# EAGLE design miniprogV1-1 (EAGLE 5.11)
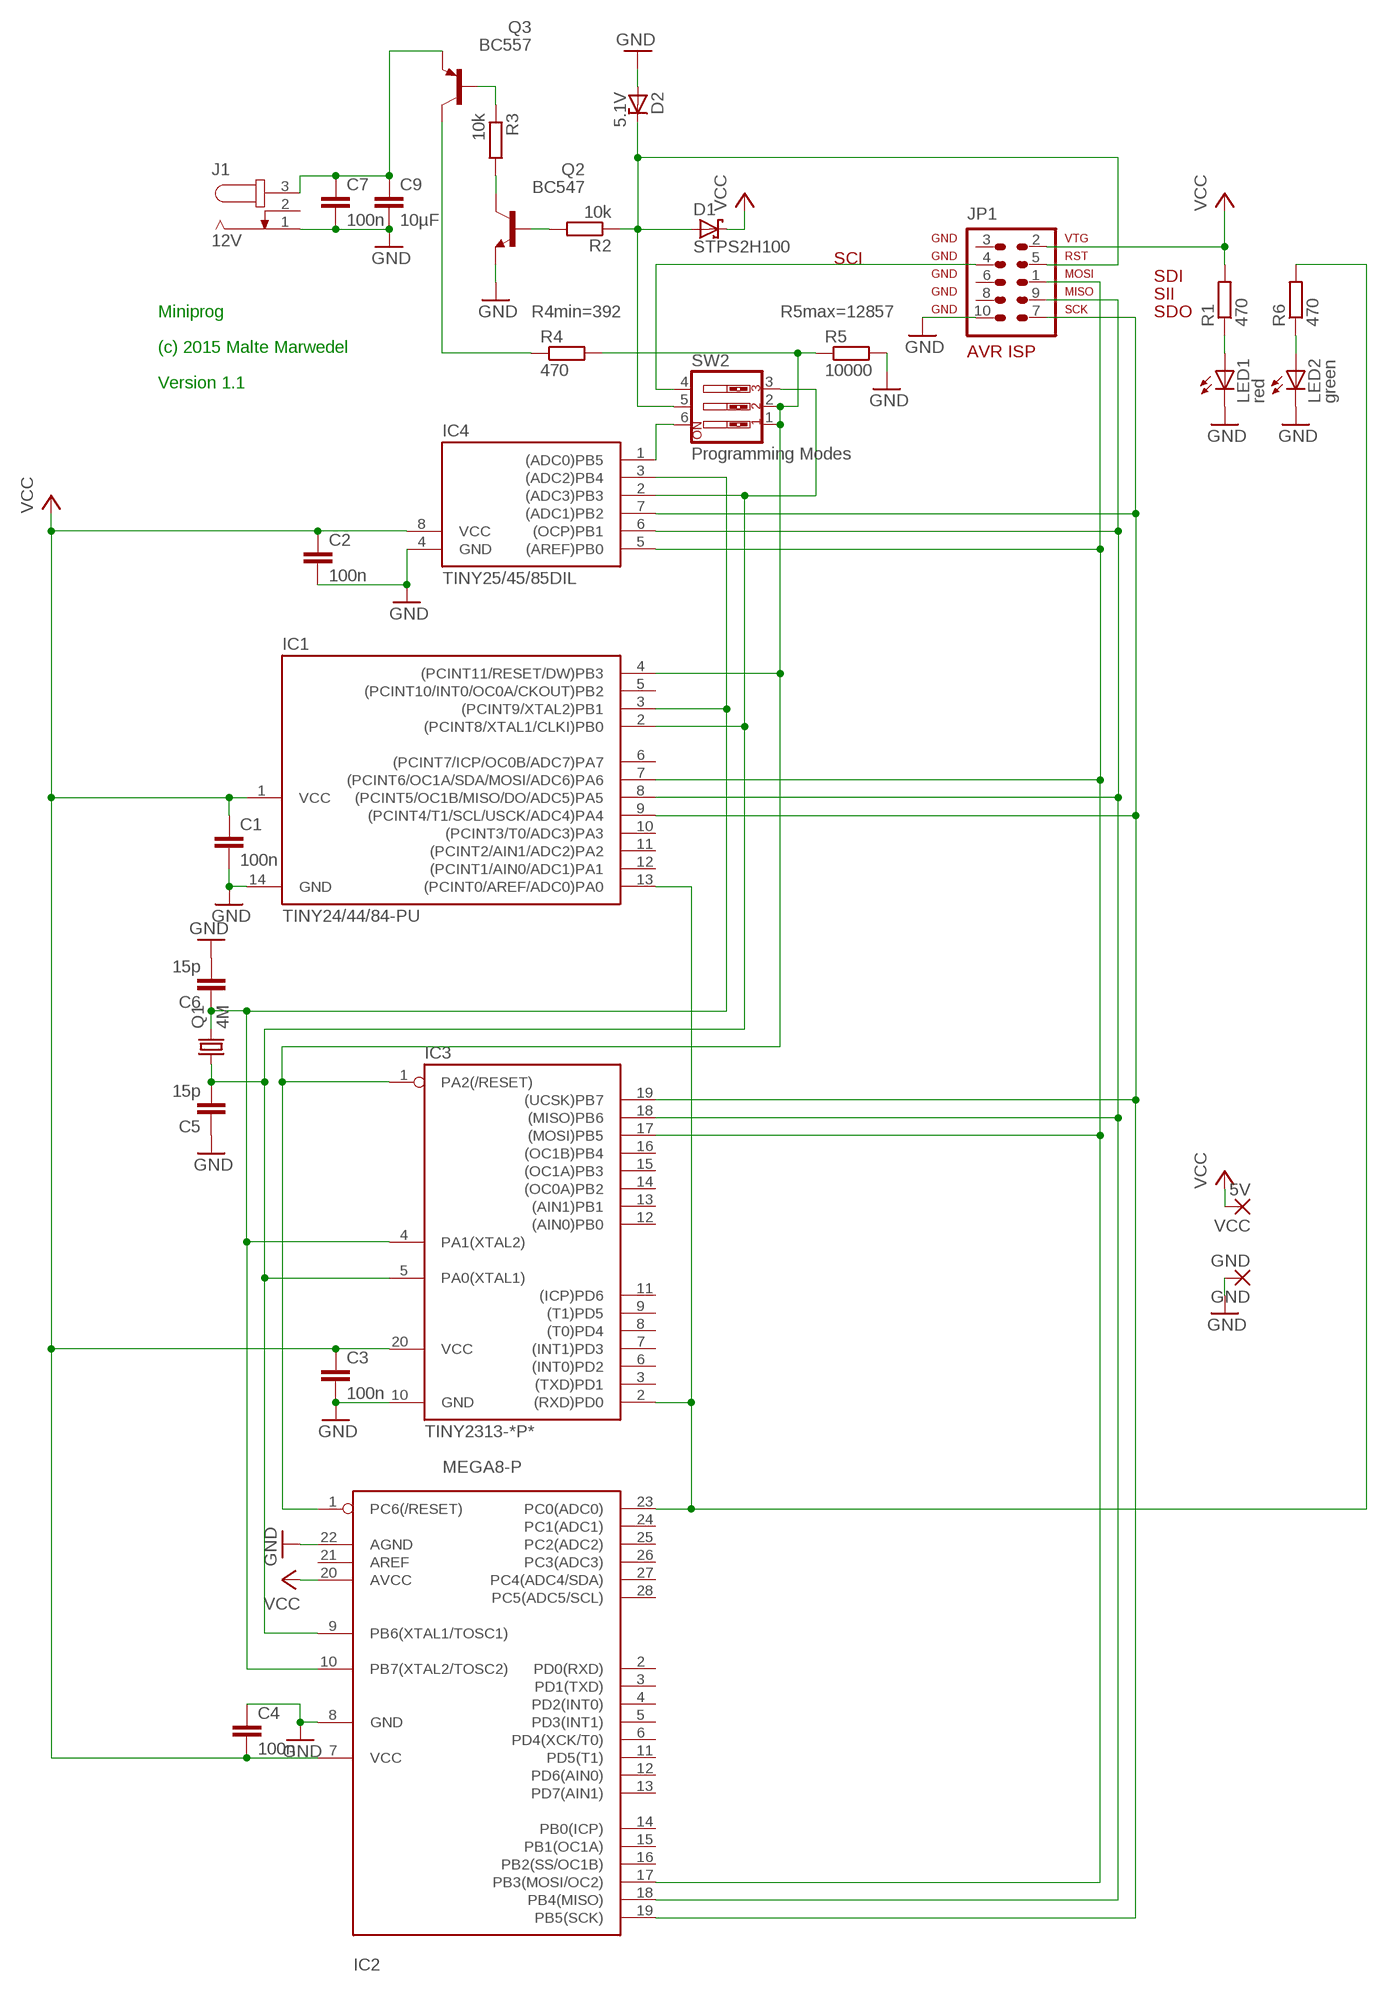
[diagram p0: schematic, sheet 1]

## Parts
C1  100n  C-EUC0805  [C0805]
C2  100n  C-EUC0805  [C0805]
C3  100n  C-EUC0805  [C0805]
C4  100n  C-EUC0805  [C0805]
C5  15p  C-EUC0805  [C0805]
C6  15p  C-EUC0805  [C0805]
C7  100n  C-EUC0805  [C0805]
C9  10µF  C-EUC0805  [C0805]
D1  STPS2H100  SCHOTTKY-DIODEDO35-7  [DO35-7]
D2  5.1V  ZENER-DIODEDO35Z10  [DO35Z10]
GND  GND  1,6/0,8  [1,6/0,8]
IC1  TINY24/44/84-PU  [DIL14]
IC2  MEGA8-P  [DIL28-3]
IC3  TINY2313-*P*  [DIL20]
IC4  TINY25/45/85DIL  [DIL08]
J1  12V  JACK-PLUG  [HEBW21]
JP1  AVR-ISP-10  [AVR-ISP-10]
LED1  red  LEDCHIPLED_0805  [CHIPLED_0805]
LED2  green  LEDCHIPLED_0805  [CHIPLED_0805]
Q1  4M  CRYSTALHC18U-V  [HC18U-V]
Q2  BC547  [TO92]
Q3  BC557  [TO92]
R1  470  R-EU_R0805  [R0805]
R2  10k  R-EU_R0805  [R0805]
R3  10k  R-EU_R0805  [R0805]
R4  470  R-EU_R0805  [R0805]
R5  10000  R-EU_R0805  [R0805]
R6  470  R-EU_R0805  [R0805]
SW2  Programming Modes  SW_DIP-3  [EDG-03]
VCC  5V  1,6/0,8  [1,6/0,8]

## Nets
GND: C1.2 C2.2 C3.2 C4.1 C5.1 C6.2 C7.2 C9.2 D2.A GND.1(P) IC1.14(GND) IC2.8(GND) IC2.22(AGND) IC3.10(GND) IC4.4(GND) J1.1 JP1.10 LED1.C LED2.C Q2.1(E) R5.2
N$1: IC4.1((ADC0)PB5) SW2.6
N$2: C7.1 C9.1 J1.3 Q3.1(E)
N$3: IC1.4((PCINT11/RESET/DW)PB3) IC2.1(PC6(/RESET)) IC3.1(PA2(/RESET)) R4.2 R5.1 SW2.1 SW2.2
N$4: IC1.9((PCINT4/T1/SCL/USCK/ADC4)PA4) IC2.19(PB5(SCK)) IC3.19((UCSK)PB7) IC4.7((ADC1)PB2) JP1.7
N$5: LED1.A R1.1
N$6: IC1.8((PCINT5/OC1B/MISO/DO/ADC5)PA5) IC2.18(PB4(MISO)) IC3.18((MISO)PB6) IC4.6((OCP)PB1) JP1.9
N$7: IC1.7((PCINT6/OC1A/SDA/MOSI/ADC6)PA6) IC2.17(PB3(MOSI/OC2)) IC3.17((MOSI)PB5) IC4.5((AREF)PB0) JP1.1
N$8: C5.2 IC1.2((PCINT8/XTAL1/CLKI)PB0) IC2.9(PB6(XTAL1/TOSC1)) IC3.5(PA0(XTAL1)) IC4.2((ADC3)PB3) Q1.1 SW2.3
N$9: C6.1 IC1.3((PCINT9/XTAL2)PB1) IC2.10(PB7(XTAL2/TOSC2)) IC3.4(PA1(XTAL2)) IC4.3((ADC2)PB4) Q1.2
N$10: JP1.4 SW2.4
N$11: Q2.2(B) R2.2
N$12: D1.A D2.C JP1.5 R2.1 SW2.5
N$13: Q3.3(C) R4.1
N$14: Q3.2(B) R3.1
N$15: Q2.3(C) R3.2
N$16: LED2.A R6.1
N$17: IC1.13((PCINT0/AREF/ADC0)PA0) IC2.23(PC0(ADC0)) IC3.2((RXD)PD0) R6.2
VCC: C1.1 C2.1 C3.1 C4.2 D1.C IC1.1(VCC) IC2.7(VCC) IC2.20(AVCC) IC3.20(VCC) IC4.8(VCC) JP1.2 R1.2 VCC.1(P)
Unconnected: IC1.5((PCINT10/INT0/OC0A/CKOUT)PB2) IC1.6((PCINT7/ICP/OC0B/ADC7)PA7) IC1.10((PCINT3/T0/ADC3)PA3) IC1.11((PCINT2/AIN1/ADC2)PA2) IC1.12((PCINT1/AIN0/ADC1)PA1) IC2.2(PD0(RXD)) IC2.3(PD1(TXD)) IC2.4(PD2(INT0)) IC2.5(PD3(INT1)) IC2.6(PD4(XCK/T0)) IC2.11(PD5(T1)) IC2.12(PD6(AIN0)) IC2.13(PD7(AIN1)) IC2.14(PB0(ICP)) IC2.15(PB1(OC1A)) IC2.16(PB2(SS/OC1B)) IC2.21(AREF) IC2.24(PC1(ADC1)) IC2.25(PC2(ADC2)) IC2.26(PC3(ADC3)) IC2.27(PC4(ADC4/SDA)) IC2.28(PC5(ADC5/SCL)) IC3.3((TXD)PD1) IC3.6((INT0)PD2) IC3.7((INT1)PD3) IC3.8((T0)PD4) IC3.9((T1)PD5) IC3.11((ICP)PD6) IC3.12((AIN0)PB0) IC3.13((AIN1)PB1) IC3.14((OC0A)PB2) IC3.15((OC1A)PB3) IC3.16((OC1B)PB4) J1.2 JP1.3 JP1.6 JP1.8

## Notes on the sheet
- SCI
- SDI
- SII
- Miniprog | R4min=392 | R5max=12857 | SDO
- (c) 2015 Malte Marwedel
- Version 1.1

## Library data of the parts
C1-C7 C9 = rcl:C-EU: CAPACITOR, European symbol
D1 = adafruit:SCHOTTKY-DIODE: Schottky Diode
D2 = diode:ZENER-DIODE: Z-Diode
GND VCC = wirepad:1,6/0,8: THROUGH-HOLE PAD
IC1 = avr-7:TINY24/44/84
IC2 = avr-7:MEGA8-P: MICROCONTROLLER 8 Kbytes FLASH 1 kbytes SRAM 512 bytes EEPROM USART 4-channel 10 bit ADC 2-channel 8 bit ADC
IC3 = avr-7:TINY2313*: Atmel Tiny2313 2K Flash, 128 bytes EEPROM, 128 bytes RAM
IC4 = avr-7:TINY25/45/85
J1 = maltes2_lib:JACK-PLUG: DC POWER JACK Power Jack, DC, Right Angle, Through Hole, Rated 5A at 16VDC, PC Terminals Distributor: Farnell (www.Farnell.de) Drawing: 84N1161.pdf / 84N1162.pdf Manufacturer: SPC Technology (www.spctechnology.com) Type: SPC4077 / SPC 4078
JP1 = avr-7:AVR-ISP-10: AVR ISP-10 Serial Programming Header
LED1 LED2 = adafruit:LED: LED
Q1 = crystal:CRYSTAL: CRYSTAL; OC_FARNELL: unknown; OC_NEWARK: unknown
Q2 = transistor-npn:BC547*: NPN Transistor
Q3 = transistor-pnp:BC557: PNP Transistor
R1-R6 = rcl:R-EU_: RESISTOR, European symbol
SW2 = special:SW_DIP-3: DIP SWITCH

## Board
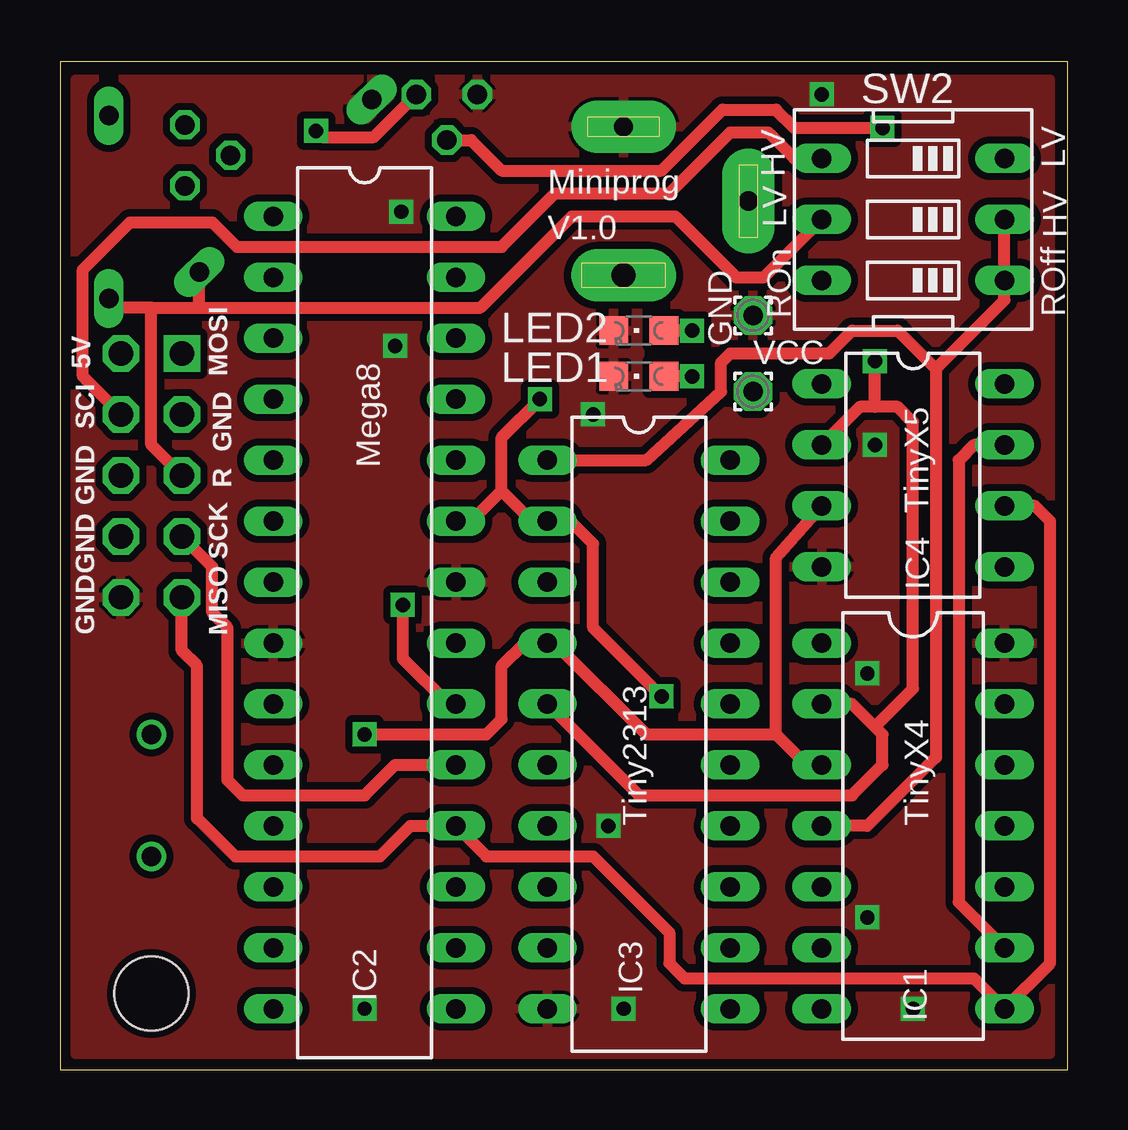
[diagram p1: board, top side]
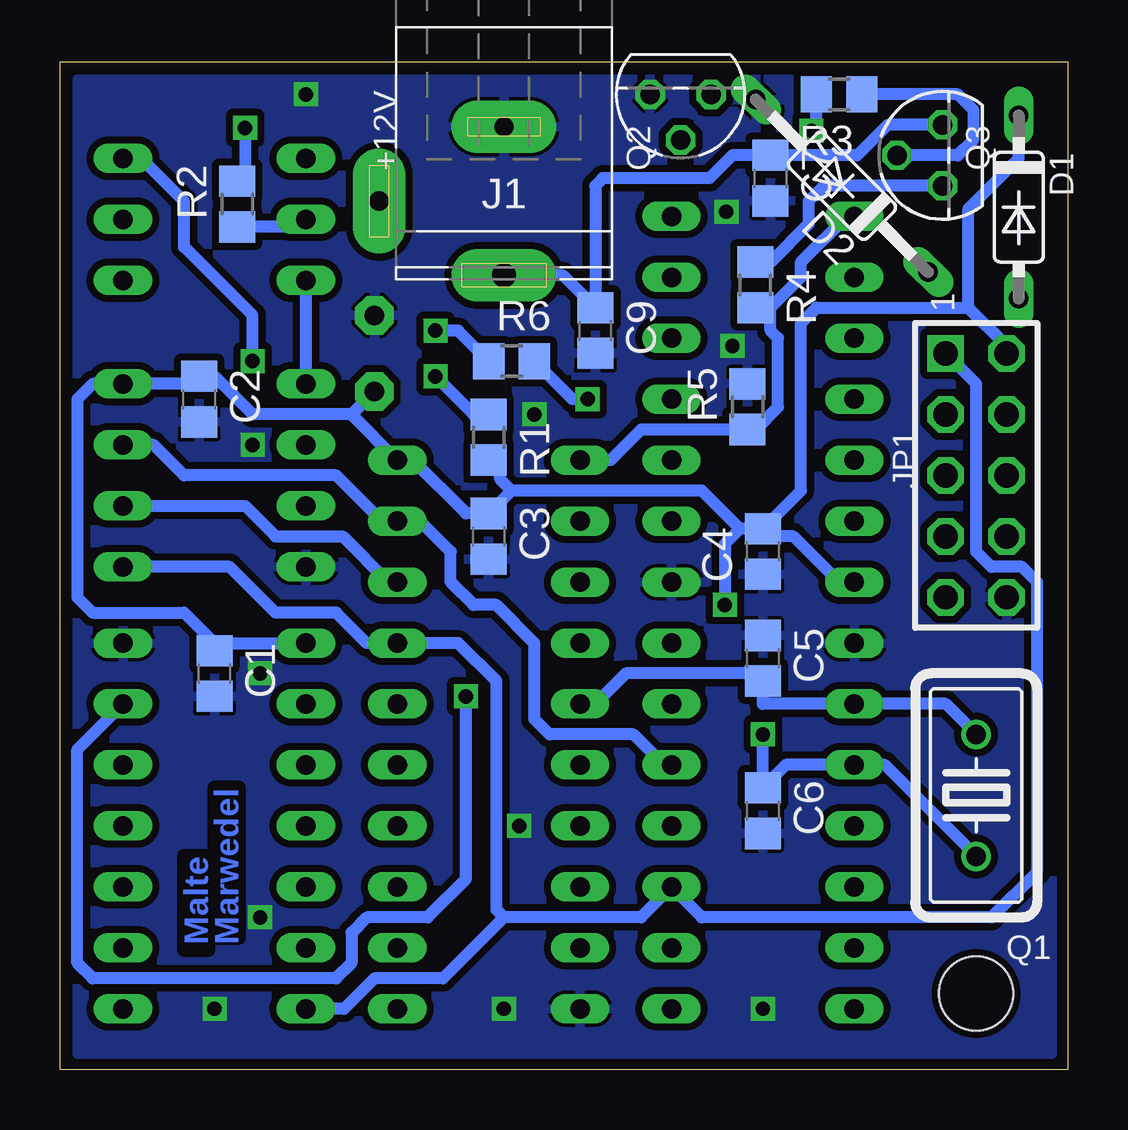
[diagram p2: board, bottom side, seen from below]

Size 42 x 42 mm. Coordinates in mm from the lower left corner, seen from the top.
Outline: 0,0 42,0 42,42 0,42 0,0
Copper layers (1*16): Top 0.035mm / dielectric 1.5mm / Bottom 0.035mm
Design rules "platinensammler_02": minimum track width 0.15mm, minimum drill 0.3mm, track to track 0.15mm, track to pad 0.15mm, pad to pad 0.15mm, via to via 0.15mm, smd to smd 0mil, copper to edge 0.2mm, drill to drill 0.2mm, minimum pad ring 0.2mm, minimum via ring 0.2mm, stop-mask expansion 4mil, vias tented up to drill 0.8mm, thermal gap 0.15mm
Holes 3.1 mm at 3.81,3.17

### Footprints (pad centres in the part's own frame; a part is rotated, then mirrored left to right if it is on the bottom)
C0805 = smd 1.3 x 1.5: 1 -0.95,0; 2 0.95,0
DO35-7 = drill 0.813 long: A 3.81,0; C -3.81,0
DO35Z10 = drill 0.813 long: A 5.08,0; C -5.08,0
1,6/0,8 = drill 0.813 pad 1.6 octagon: 1 0,0
DIL14 = drill 0.813 long: 1 -7.62,-3.81; 2 -5.08,-3.81; 3 -2.54,-3.81; 4 0,-3.81; 5 2.54,-3.81; 6 5.08,-3.81; 7 7.62,-3.81; 8 7.62,3.81; 9 5.08,3.81; 10 2.54,3.81; 11 0,3.81; 12 -2.54,3.81; 13 -5.08,3.81; 14 -7.62,3.81
DIL28-3 = drill 0.813 long: 1 -16.51,-3.81; 2 -13.97,-3.81; 3 -11.43,-3.81; 4 -8.89,-3.81; 5 -6.35,-3.81; 6 -3.81,-3.81; 7 -1.27,-3.81; 8 1.27,-3.81; 9 3.81,-3.81; 10 6.35,-3.81; 11 8.89,-3.81; 12 11.43,-3.81; 13 13.97,-3.81; 14 16.51,-3.81; 15 16.51,3.81; 16 13.97,3.81; 17 11.43,3.81; 18 8.89,3.81; 19 6.35,3.81; 20 3.81,3.81; 21 1.27,3.81; 22 -1.27,3.81; 23 -3.81,3.81; 24 -6.35,3.81; 25 -8.89,3.81; 26 -11.43,3.81; 27 -13.97,3.81; 28 -16.51,3.81
DIL20 = drill 0.813 long: 1 -11.43,-3.81; 2 -8.89,-3.81; 3 -6.35,-3.81; 4 -3.81,-3.81; 5 -1.27,-3.81; 6 1.27,-3.81; 7 3.81,-3.81; 8 6.35,-3.81; 9 8.89,-3.81; 10 11.43,-3.81; 11 11.43,3.81; 12 8.89,3.81; 13 6.35,3.81; 14 3.81,3.81; 15 1.27,3.81; 16 -1.27,3.81; 17 -3.81,3.81; 18 -6.35,3.81; 19 -8.89,3.81; 20 -11.43,3.81
DIL08 = drill 0.813 long: 1 -3.81,-3.81; 2 -1.27,-3.81; 3 1.27,-3.81; 4 3.81,-3.81; 5 3.81,3.81; 6 1.27,3.81; 7 -1.27,3.81; 8 -3.81,3.81
HEBW21 = drill 0.8 pad 2.184 long: 1 -3.1,0; 2 0,-5.2 | drill 1 pad 2.184 long: 3 3.1,0
AVR-ISP-10 = drill 1.016 square: 1 -5.08,-1.27 | drill 1.016 octagon: 2 -5.08,1.27; 3 -2.54,-1.27; 4 -2.54,1.27; 5 0,-1.27; 6 0,1.27; 7 2.54,-1.27; 8 2.54,1.27; 9 5.08,-1.27; 10 5.08,1.27
CHIPLED_0805 = smd 1.2 x 1.2: A 0,-1.05; C 0,1.05
HC18U-V = drill 0.813 round: 1 -2.54,0; 2 2.54,0
TO92 = drill 0.813 octagon: 1 1.27,0; 2 0,1.905; 3 -1.27,0
R0805 = smd 1.3 x 1.5: 1 -0.95,0; 2 0.95,0
EDG-03 = drill 0.813 long: 1 -2.54,-3.81; 2 0,-3.81; 3 2.54,-3.81; 4 2.54,3.81; 5 0,3.81; 6 -2.54,3.81

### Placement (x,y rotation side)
C1  35.56,16.51 270 bottom
C2  36.2,27.94 270 bottom
C3  24.13,22.23 270 bottom
C4  12.7,21.59 90 bottom
C5  12.7,17.14 270 bottom
C6  12.7,10.79 270 bottom
C7  12.38,37.15 270 bottom
C9  19.68,30.8 270 bottom
D1  2.03,35.94 270 bottom
D2  9.4,36.83 135 bottom
GND  28.89,31.43 0 top
IC1  35.56,10.16 270 top
IC2  12.7,19.05 270 top
IC3  24.13,13.97 270 top
IC4  35.56,24.77 270 top
J1  23.5,36.2 270 bottom
JP1  3.81,24.77 270 bottom
LED1  24.13,28.89 90 top
LED2  24.13,30.8 90 top
Q1  3.81,11.43 270 bottom
Q2  16.13,40.64 180 bottom
Q3  5.21,38.1 90 bottom
R1  24.13,26.35 270 bottom
R2  34.61,36.07 90 bottom
R3  9.53,40.64 180 bottom
R4  13.02,32.7 270 bottom
R5  13.34,27.62 90 bottom
R6  23.18,29.53 0 bottom
SW2  35.56,35.43 90 top
VCC  28.89,28.26 0 top

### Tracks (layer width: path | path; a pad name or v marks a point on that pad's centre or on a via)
GND  (via drill 0.6)
  other vias: 12.7,2.54 23.5,2.54 35.56,2.54 33.97,26.04 31.75,40.64 22.86,10.16 14.22,35.75 33.66,6.35 22.23,27.3 33.66,16.51 13.97,30.16
  pour Top (isolate 0.3): 0.64,41.27 41.27,41.27 41.27,0.64 0.64,0.64
  pour Bottom (isolate 0.3): 0.64,41.27 41.27,41.27 41.27,0.64 0.64,0.64
N$1
  Bottom 0.5: IC4.1 SW2.6
N$2
  Bottom 0.5: Q3.1 7.49,39.37 8.76,38.1 C7.1 13.97,38.1 14.92,37.15 19.37,37.15 19.68,36.83 C9.1 21.03,33.09 J1.3
N$3
  Top 0.5: IC1.4 33.66,10.16 36.51,13.02 36.51,29.21 | 36.51,29.21 39.37,32.07 SW2.1 SW2.2 | 36.51,29.21 34.92,30.8 33.02,30.8 32.07,29.84 27.94,29.84 27.56,29.46 27.56,28.26 24.45,25.4 IC3.1
  Bottom 0.5: IC3.1 19.05,25.4 17.78,26.67 14.29,26.67 R5.1 13.02,26.67 12.06,27.62 12.06,30.48 12.38,30.8 12.38,31.75 | 12.38,31.75 12.06,32.07 11.11,33.02 11.11,33.66 9.21,35.56 IC2.1 | 12.38,31.75 R4.2
N$4
  Top 0.5: IC1.9 37.47,6.99 37.47,25.4 38.1,26.04 IC4.7 | IC2.19 13.97,12.7 12.7,11.43 7.62,11.43 6.99,12.06 6.99,18.41 6.35,19.05 6.35,20.95 JP1.7
  Bottom 0.5: IC4.7 38.1,26.04 36.83,24.77 30.48,24.77 28.57,22.86 IC3.19 26.99,22.86 25.72,21.59 25.72,20.32 24.77,19.37 23.81,19.37 22.23,17.78 22.23,14.61 21.59,13.97 18.1,13.97 16.83,12.7 IC2.19
N$5  (via drill 0.6)
  Top 0.5: v26.35,28.89 LED1.A
  Bottom 0.5: v26.35,28.89 24.76,27.3 R1.1
N$6
  Top 0.5: IC4.6 40.64,23.5 41.27,22.86 41.27,4.45 IC1.8 38.1,3.81 26.04,3.81 25.4,4.45 25.4,5.71 22.23,8.89 17.78,8.89 IC2.18 14.61,10.16 13.34,8.89 7.3,8.89 5.71,10.48 5.71,16.83 5.08,17.46 JP1.9
  Bottom 0.5: IC4.6 34.29,23.5 33.02,22.23 30.23,22.23 28.32,20.32 IC3.18
N$7
  Bottom 0.5: 23.5,6.35 17.78,6.35 IC2.17 15.24,6.35 3.17,6.35 1.27,8.26 1.27,20.32 1.91,20.95 3.17,20.95 3.81,21.59 3.81,28.57 JP1.1 | 23.5,6.35 26.04,3.81 28.89,3.81 30.16,2.54 IC1.7 | 23.5,6.35 23.81,6.67 23.81,16.19 25.4,17.78 IC3.17 29.21,17.78 30.48,19.05 33.02,19.05 34.92,20.95 IC4.5
N$8  (via drill 0.6)
  Top 0.5: IC3.5 24.13,11.43 33.02,11.43 34.29,12.7 34.29,13.97 33.97,14.29 | 33.97,14.29 33.02,15.24 IC1.2 | 33.97,27.62 33.34,27.62 32.07,26.35 32.07,26.04 | 32.07,26.04 32.38,26.04 | 32.07,26.04 IC4.2 | 33.97,27.62 34.92,27.62 35.56,26.99 35.56,15.88 33.97,14.29 | 33.97,27.62 v33.97,29.53
  Bottom 0.5: Q1.1 5.08,15.24 IC2.9 12.7,15.24 C5.2 13.02,16.51 18.41,16.51 19.68,15.24 IC3.5 | v33.97,29.53 33.97,31.43 36.83,34.29 36.83,36.2 38.61,37.97 SW2.3
N$9  (via drill 0.6)
  Top 0.5: 29.84,13.97 24.45,13.97 20.64,17.78 IC3.4 19.37,17.78 18.41,16.83 18.41,14.61 17.78,13.97 v12.7,13.97 | 29.84,13.97 31.11,12.7 IC1.3 | IC4.3 29.84,21.34 29.84,13.97
  Bottom 0.5: Q1.2 7.62,12.7 IC2.10 11.74,12.7 C6.1 v12.7,13.97
N$10
  Top 0.5: JP1.4 0.95,28.89 0.95,33.34 2.92,35.31 6.35,35.31 7.37,34.29 18.41,34.29 20.64,36.51 25.4,36.51 27.94,39.05 29.53,39.05 30.61,37.97 SW2.4
N$11  (via drill 0.6)
  Top 0.5: Q2.2 17.14,38.73 18.41,37.47 25.08,37.47 27.62,40.01 29.84,40.01 30.61,39.24 v34.29,39.24
  Bottom 0.5: v34.29,39.24 34.29,37.47 R2.2
N$12
  Top 0.5: JP1.5 3.81,26.04 3.81,31.75 | 3.81,31.75 5.84,31.75 | 5.84,31.75 17.53,31.75 21.34,35.56 25.65,35.56 28.19,33.02 29.34,33.02 SW2.5 | 3.81,31.75 2.41,31.75 D1.A | D2.C 5.81,31.79 5.84,31.75
  Bottom 0.5: 34.93,34.92 R2.1 32.06,35.12 SW2.5
N$13
  Bottom 0.5: R4.1 12.38,33.65 10.79,35.24 10.8,36.19 10.16,36.83 Q3.3
N$14
  Bottom 0.5: Q3.2 4.57,38.1 3.94,38.73 3.94,40.01 4.57,40.64 R3.1
N$15  (via drill 0.6)
  Top 0.5: Q2.3 13.08,38.86 10.92,38.86 v10.67,39.12
  Bottom 0.5: v10.67,39.12 10.47,39.31 R3.2
N$16  (via drill 0.6)
  Top 0.5: v26.35,30.8 LED2.A
  Bottom 0.5: v26.35,30.8 25.4,30.8 R6.1
N$17  (via drill 0.6)
  Top 0.5: v20,27.94 18.41,26.35 18.41,24.13 | 18.41,24.13 17.14,22.86 IC2.23 | 18.41,24.13 19.68,22.86 IC3.2 21.27,22.86 22.23,21.91 22.23,18.41 v25.08,15.56
  Bottom 0.5: R6.2 20.64,27.94 v20,27.94 | IC1.13 41.27,13.34 41.27,4.45 40.64,3.81 30.48,3.81 29.84,4.45 29.84,5.71 29.21,6.35 26.67,6.35 25.08,7.94 v25.08,15.56
VCC  (via drill 0.6)
  Top 0.5: IC2.20 16.19,15.24 14.29,17.14 v14.29,19.37
  Bottom 0.5: IC2.7 9.84,20.32 9.84,20.64 11.43,22.23 12.38,22.23 C4.2 | 35.24,17.78 C1.1 | 35.24,17.78 IC1.1 | 35.24,17.78 35.56,17.78 36.83,19.05 40.64,19.05 41.27,19.68 41.27,27.94 40.64,28.57 IC4.8 35.88,28.57 C2.1 35.56,28.89 35.24,28.57 33.97,27.3 29.84,27.3 | JP1.2 2.54,30.16 4.13,31.75 | 4.13,31.75 10.48,31.75 11.11,31.11 11.11,24.13 C4.2 | 4.13,31.75 4.13,35.88 2.03,37.97 D1.C | 13.65,22.54 15.24,24.13 23.18,24.13 | 13.65,22.54 C4.2 | v14.29,19.37 14.29,21.91 13.65,22.54 | 29.84,27.3 IC3.20 27.3,25.4 25.08,23.18 C3.1 23.18,24.13 | 29.84,27.3 VCC.1 | R1.2 23.65,24.93 23.65,24.61 23.18,24.13

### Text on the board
Bottom: Marwedel | Malte
tNames: HV | LV | Miniprog | LV | HV | V1.0 | ROn | ROff | SCI | 5V | MOSI | GND | GND | R | Mega8 | GND | TinyX5 | GND | SCK | MISO | Tiny2313 | TinyX4
bNames: +12V | 1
